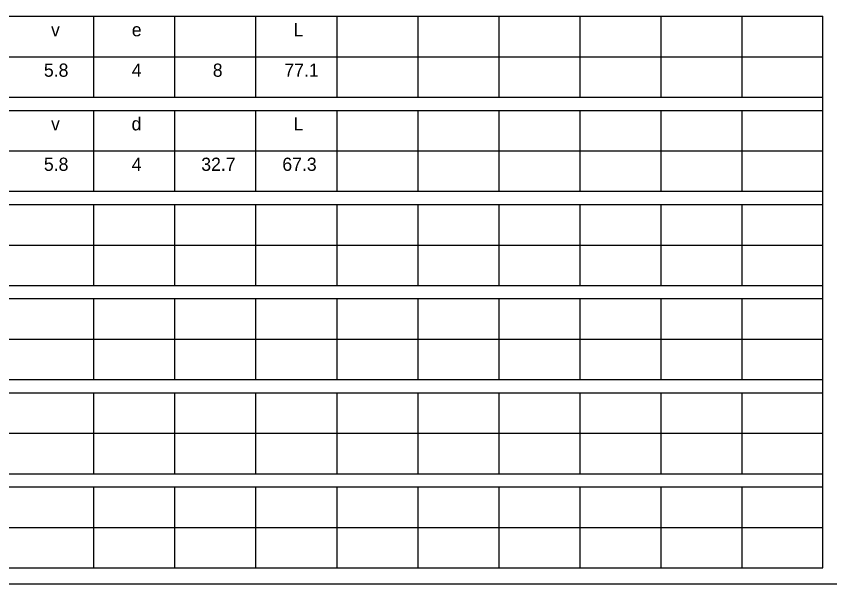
# Model space of a CAD drawing. Extents: x 1374 to 1480, y 568 to 638.
# Drawn here: x 1417.68 to 1428.25, y 587.83 to 595.21 of the extents above; entities that cross this region are included whole.
import ezdxf

# ---------------------------------------------------------------- set-up
doc = ezdxf.new("R2010")
doc.units = 0
doc.layers.add('GSSign', color=7, linetype='Continuous')
doc.layers.add('SheetLinesMisc2_dp', color=7, linetype='Continuous')

msp = doc.modelspace()

# ---------------------------------------------------------------- linework, layer by layer
at = {"layer": 'SheetLinesMisc2_dp'}
for p, q in [((1402.268, 595.208), (1428.163, 595.208)), ((1418.683, 595.208), (1418.683, 594.156)), ((1419.736, 595.208), (1419.736, 594.156)), ((1420.789, 595.208), (1420.789, 594.156)), ((1421.843, 595.208), (1421.843, 594.156)), ((1422.896, 595.208), (1422.896, 594.156)), ((1423.95, 595.208), (1423.95, 594.156)), ((1425.003, 595.208), (1425.003, 594.156)), ((1426.056, 595.208), (1426.056, 594.156)), ((1427.11, 595.208), (1427.11, 594.156)), ((1428.163, 588.039), (1428.163, 595.208)), ((1402.268, 594.682), (1428.163, 594.682)), ((1402.268, 594.156), (1428.163, 594.156)), ((1402.268, 593.985), (1428.163, 593.985)), ((1418.683, 593.985), (1418.683, 592.933)), ((1419.736, 593.985), (1419.736, 592.933)), ((1420.789, 593.985), (1420.789, 592.933)), ((1421.843, 593.985), (1421.843, 592.933)), ((1422.896, 593.985), (1422.896, 592.933)), ((1423.95, 593.985), (1423.95, 592.933)), ((1425.003, 593.985), (1425.003, 592.933)), ((1426.056, 593.985), (1426.056, 592.933)), ((1427.11, 593.985), (1427.11, 592.933)), ((1402.268, 593.459), (1428.163, 593.459)), ((1402.268, 592.933), (1428.163, 592.933)), ((1402.268, 592.761), (1428.163, 592.761)), ((1418.683, 592.761), (1418.683, 591.709)), ((1419.736, 592.761), (1419.736, 591.709)), ((1420.789, 592.761), (1420.789, 591.709)), ((1421.843, 592.761), (1421.843, 591.709)), ((1422.896, 592.761), (1422.896, 591.709)), ((1423.95, 592.761), (1423.95, 591.709)), ((1425.003, 592.761), (1425.003, 591.709)), ((1426.056, 592.761), (1426.056, 591.709)), ((1427.11, 592.761), (1427.11, 591.709)), ((1402.268, 592.235), (1428.163, 592.235)), ((1402.268, 591.709), (1428.163, 591.709)), ((1402.268, 591.538), (1428.163, 591.538)), ((1418.683, 591.538), (1418.683, 590.486)), ((1419.736, 591.538), (1419.736, 590.486)), ((1420.789, 591.538), (1420.789, 590.486)), ((1421.843, 591.538), (1421.843, 590.486)), ((1422.896, 591.538), (1422.896, 590.486)), ((1423.95, 591.538), (1423.95, 590.486)), ((1425.003, 591.538), (1425.003, 590.486)), ((1426.056, 591.538), (1426.056, 590.486)), ((1427.11, 591.538), (1427.11, 590.486)), ((1402.268, 591.012), (1428.163, 591.012)), ((1402.268, 590.486), (1428.163, 590.486)), ((1402.268, 590.314), (1428.163, 590.314)), ((1418.683, 590.314), (1418.683, 589.262)), ((1419.736, 590.314), (1419.736, 589.262)), ((1420.789, 590.314), (1420.789, 589.262)), ((1421.843, 590.314), (1421.843, 589.262)), ((1422.896, 590.314), (1422.896, 589.262)), ((1423.95, 590.314), (1423.95, 589.262)), ((1425.003, 590.314), (1425.003, 589.262)), ((1426.056, 590.314), (1426.056, 589.262)), ((1427.11, 590.314), (1427.11, 589.262)), ((1402.268, 589.788), (1428.163, 589.788)), ((1402.268, 589.262), (1428.163, 589.262)), ((1402.268, 589.09), (1428.163, 589.09)), ((1418.683, 589.09), (1418.683, 588.039)), ((1419.736, 589.09), (1419.736, 588.039)), ((1420.789, 589.09), (1420.789, 588.039)), ((1421.843, 589.09), (1421.843, 588.039)), ((1422.896, 589.09), (1422.896, 588.039)), ((1423.95, 589.09), (1423.95, 588.039)), ((1425.003, 589.09), (1425.003, 588.039)), ((1426.056, 589.09), (1426.056, 588.039)), ((1427.11, 589.09), (1427.11, 588.039)), ((1402.268, 588.565), (1428.163, 588.565)), ((1402.268, 588.039), (1428.163, 588.039)), ((1402.016, 587.832), (1454.669, 587.832))]:
    msp.add_line(p, q, dxfattribs=at)

# ---------------------------------------------------------------- texts
at = {"layer": 'GSSign'}
for s, height, p in [('L', 0.171, (1421.282, 594.948)), ('v', 0.171, (1418.129, 594.948)), ('e', 0.171, (1419.179, 594.948)), ('5.8', 0.1715, (1418.036, 594.422)), ('4', 0.171, (1419.178, 594.422)), ('8', 0.171, (1420.232, 594.422)), ('77.1', 0.1715, (1421.162, 594.422)), ('v', 0.171, (1418.129, 593.725)), ('d', 0.171, (1419.176, 593.725)), ('L', 0.171, (1421.282, 593.725)), ('5.8', 0.1715, (1418.036, 593.199)), ('4', 0.171, (1419.178, 593.199)), ('32.7', 0.1715, (1420.082, 593.199)), ('67.3', 0.1715, (1421.136, 593.199))]:
    msp.add_text(s, height=height, dxfattribs=at).set_placement(p)

doc.saveas('drawing.dxf')
